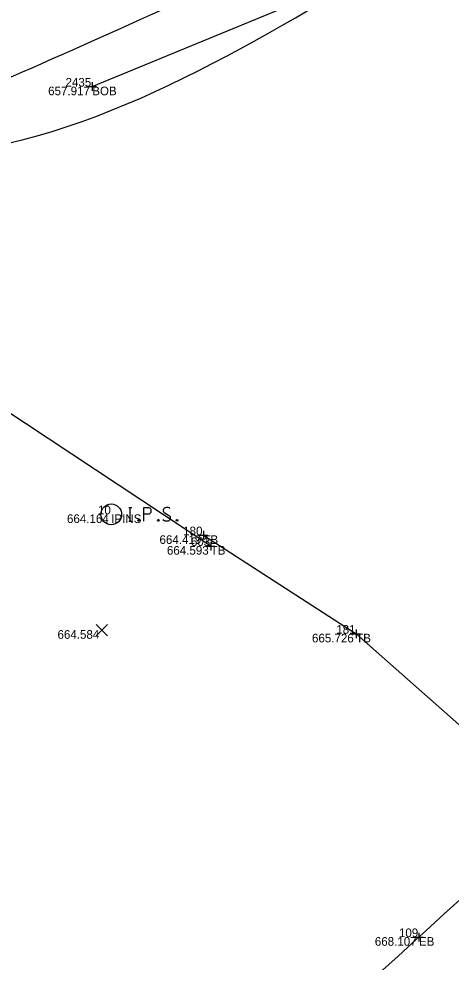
# Model space of a CAD drawing. Extents: x 2197382 to 2204062, y 634117 to 636522.
# Drawn here: x 2202463 to 2202513, y 635122.7 to 635231.8 of the extents above; entities that cross this region are included whole.
import ezdxf

# ---------------------------------------------------------------- set-up
doc = ezdxf.new("R2010")
doc.units = 0
for name, color, linetype in [('_CIVIL_CONSTRUCTION', 7, 'Continuous'), ('BR_X_SV_Bottom_of_Beam', 7, 'Continuous'), ('BR_X_SV_Bottom_of_Beam_Text', 7, 'Continuous'), ('BR_X_SV_Deck_Top', 7, 'Continuous'), ('GE_P_Alignment_100_Distances', 7, 'Continuous'), ('GE_X_Alignment', 7, 'Continuous'), ('PF_P_Grade_Line', 7, 'Continuous'), ('RW_X_CL_100_Curve_Data', 7, 'Continuous'), ('SC_Scratch1', 7, 'Continuous'), ('SH_Border', 7, 'Continuous'), ('SH_Cut_Line', 7, 'Continuous'), ('SH_Data', 7, 'Continuous')]:
    doc.layers.add(name, color=color, linetype=linetype)

msp = doc.modelspace()

# ---------------------------------------------------------------- linework, layer by layer
at = {"layer": '_CIVIL_CONSTRUCTION'}
for p, q in [((2202471.48, 635224.49), (2202471.48, 635223.49)), ((2202470.98, 635223.99), (2202471.98, 635223.99)), ((2202471.48, 635223.99), (2202471.48, 635223.99)), ((2202483.84, 635172.09), (2202484.84, 635172.09)), ((2202484.34, 635172.59), (2202484.34, 635171.59)), ((2202484.34, 635172.09), (2202484.34, 635172.09)), ((2202485.18, 635171.35), (2202485.18, 635170.35)), ((2202484.68, 635170.85), (2202485.68, 635170.85)), ((2202485.18, 635170.85), (2202485.18, 635170.85)), ((2202502.01, 635161.2), (2202502.01, 635160.2)), ((2202501.51, 635160.7), (2202502.51, 635160.7)), ((2202502.01, 635160.7), (2202502.01, 635160.7)), ((2202508.77, 635125.61), (2202509.77, 635125.61)), ((2202509.27, 635126.11), (2202509.27, 635125.11)), ((2202509.27, 635125.61), (2202509.27, 635125.61))]:
    msp.add_line(p, q, dxfattribs=at)
at = {"layer": 'BR_X_SV_Bottom_of_Beam'}
msp.add_line((2202471.48, 635223.99), (2202495.2, 635233.74), dxfattribs=at)
at = {"layer": 'BR_X_SV_Deck_Top'}
msp.add_open_spline([(2202458.05, 635216.68), (2202477.12, 635219.98), (2202511.72, 635243.78), (2202554.96, 635262.3), (2202588.01, 635280.67), (2202608.34, 635292.39), (2202640.83, 635312.14), (2202668.15, 635329.95), (2202698.57, 635351.31), (2202722.13, 635368.65), (2202754.6, 635393.43), (2202777.49, 635412.29), (2202789.61, 635422.64)], degree=3, dxfattribs=at)
at = {"layer": 'GE_P_Alignment_100_Distances'}
msp.add_open_spline([(2202457.67, 635223.28), (2202466.48, 635226.87), (2202500.46, 635242.35), (2202539.48, 635261.18), (2202573.06, 635279.52), (2202585.61, 635286.63), (2202599.84, 635294.84), (2202617.62, 635305.23), (2202642.29, 635320.4), (2202667.37, 635336.77), (2202691.72, 635353.63), (2202713.41, 635369.4), (2202739.64, 635388.97), (2202758.66, 635404.28), (2202770.06, 635413.81)], degree=3, dxfattribs=at)
at = {"layer": 'GE_X_Alignment'}
for points in [[(2202540.06, 635152.93), (2202529.43, 635144.25), (2202507.23, 635123.46), (2202471.72, 635092.05), (2202435.62, 635056.76), (2202402.1, 635018.87), (2202368.73, 634981.48), (2202336.15, 634943.25), (2202304.62, 634904.21), (2202274.11, 634864.33), (2202244.37, 634823.83), (2202215.65, 634782.83), (2202187.65, 634741.05), (2202161.54, 634698.56), (2202134.84, 634656), (2202111.41, 634611.66), (2202087.71, 634567.52), (2202064.97, 634523.35), (2202044.2, 634477.97), (2202023.42, 634432.25), (2202003.66, 634386.18), (2201990.91, 634355.55), (2201984.79, 634340.33)], [(2202570.92, 635145.14), (2202556.1, 635132.41), (2202530.6, 635107.02), (2202492.19, 635071.28), (2202457.98, 635035.82), (2202424.73, 634999.38), (2202391.64, 634962.22), (2202359.56, 634924.46), (2202328.32, 634885.6), (2202298.37, 634846.53), (2202268.85, 634806.21), (2202240.94, 634765.59), (2202212.91, 634724.71), (2202187.2, 634682.69), (2202161.14, 634640.35), (2202137.99, 634596.95), (2202114.64, 634553.56), (2202092.28, 634509.95), (2202071.73, 634464.7), (2202050.81, 634420.11), (2202031.84, 634374.34), (2202014.23, 634328.21), (2201997.98, 634281.03), (2201983.22, 634233.69), (2201972.74, 634202.38), (2201968.03, 634186.79)]]:
    msp.add_open_spline(points, degree=3, dxfattribs=at)
at = {"layer": 'PF_P_Grade_Line'}
for points in [[(2202485.18, 635170.85), (2202458.37, 635188.56), (2202433.67, 635197.97), (2202429.22, 635201.88)], [(2202484.34, 635172.09), (2202502.01, 635160.7), (2202520.5, 635144.4), (2202527.86, 635144.47)]]:
    msp.add_lwpolyline(points, dxfattribs=at)
at = {"layer": 'RW_X_CL_100_Curve_Data'}
for p, q in [((2202471.92, 635160.45), (2202473.25, 635161.79)), ((2202471.92, 635161.79), (2202473.25, 635160.45))]:
    msp.add_line(p, q, dxfattribs=at)
at = {"layer": 'SC_Scratch1'}
for points in [[(2202475.7, 635175.31), (2202476.05, 635175.31)], [(2202475.7, 635175.31), (2202476.05, 635175.31)], [(2202475.88, 635173.71), (2202475.88, 635175.31)], [(2202475.88, 635173.71), (2202475.88, 635175.31)], [(2202477.44, 635173.71), (2202477.44, 635175.31), (2202477.97, 635175.31), (2202478.03, 635175.3), (2202478.1, 635175.27), (2202478.14, 635175.25), (2202478.17, 635175.22), (2202478.21, 635175.16), (2202478.25, 635175.1), (2202478.27, 635175), (2202478.27, 635174.84), (2202478.26, 635174.79), (2202478.24, 635174.72), (2202478.19, 635174.63), (2202478.15, 635174.59), (2202478.11, 635174.57), (2202478.06, 635174.54), (2202477.97, 635174.53), (2202477.44, 635174.53)], [(2202477.44, 635173.71), (2202477.44, 635175.31), (2202477.97, 635175.31), (2202478.03, 635175.3), (2202478.1, 635175.27), (2202478.14, 635175.25), (2202478.17, 635175.22), (2202478.21, 635175.16), (2202478.25, 635175.1), (2202478.27, 635175), (2202478.27, 635174.84), (2202478.26, 635174.79), (2202478.24, 635174.72), (2202478.19, 635174.63), (2202478.15, 635174.59), (2202478.11, 635174.57), (2202478.06, 635174.54), (2202477.97, 635174.53), (2202477.44, 635174.53)], [(2202480.45, 635175.2), (2202480.43, 635175.22), (2202480.4, 635175.25), (2202480.3, 635175.29), (2202480.18, 635175.31), (2202480.09, 635175.31), (2202480.05, 635175.31), (2202479.91, 635175.27), (2202479.79, 635175.2), (2202479.71, 635175.1), (2202479.69, 635175), (2202479.69, 635174.92), (2202479.71, 635174.82), (2202479.8, 635174.73), (2202480.41, 635174.35), (2202480.46, 635174.3), (2202480.48, 635174.25), (2202480.51, 635174.18), (2202480.51, 635174.1), (2202480.5, 635174.03), (2202480.48, 635173.98), (2202480.46, 635173.91), (2202480.44, 635173.86), (2202480.42, 635173.82), (2202480.38, 635173.79), (2202480.35, 635173.76), (2202480.31, 635173.74), (2202480.27, 635173.72), (2202480.18, 635173.71), (2202480.02, 635173.71), (2202479.92, 635173.74), (2202479.78, 635173.82), (2202479.69, 635173.9)], [(2202480.45, 635175.2), (2202480.43, 635175.22), (2202480.4, 635175.25), (2202480.3, 635175.29), (2202480.18, 635175.31), (2202480.09, 635175.31), (2202480.05, 635175.31), (2202479.91, 635175.27), (2202479.79, 635175.2), (2202479.71, 635175.1), (2202479.69, 635175), (2202479.69, 635174.92), (2202479.71, 635174.82), (2202479.8, 635174.73), (2202480.41, 635174.35), (2202480.46, 635174.3), (2202480.48, 635174.25), (2202480.51, 635174.18), (2202480.51, 635174.1), (2202480.5, 635174.03), (2202480.48, 635173.98), (2202480.46, 635173.91), (2202480.44, 635173.86), (2202480.42, 635173.82), (2202480.38, 635173.79), (2202480.35, 635173.76), (2202480.31, 635173.74), (2202480.27, 635173.72), (2202480.18, 635173.71), (2202480.02, 635173.71), (2202479.92, 635173.74), (2202479.78, 635173.82), (2202479.69, 635173.9)], [(2202475.7, 635173.71), (2202476.05, 635173.71)], [(2202475.7, 635173.71), (2202476.05, 635173.71)], [(2202476.84, 635173.92), (2202476.89, 635173.92), (2202476.92, 635173.9), (2202476.96, 635173.85), (2202476.96, 635173.79), (2202476.92, 635173.74), (2202476.89, 635173.71), (2202476.84, 635173.71), (2202476.8, 635173.74), (2202476.77, 635173.79), (2202476.77, 635173.85), (2202476.8, 635173.9), (2202476.84, 635173.92)], [(2202476.84, 635173.92), (2202476.89, 635173.92), (2202476.92, 635173.9), (2202476.96, 635173.85), (2202476.96, 635173.79), (2202476.92, 635173.74), (2202476.89, 635173.71), (2202476.84, 635173.71), (2202476.8, 635173.74), (2202476.77, 635173.79), (2202476.77, 635173.85), (2202476.8, 635173.9), (2202476.84, 635173.92)], [(2202479.08, 635173.92), (2202479.14, 635173.92), (2202479.17, 635173.9), (2202479.21, 635173.85), (2202479.21, 635173.79), (2202479.17, 635173.74), (2202479.14, 635173.71), (2202479.08, 635173.71), (2202479.05, 635173.74), (2202479.02, 635173.79), (2202479.02, 635173.85), (2202479.05, 635173.9), (2202479.08, 635173.92)], [(2202479.08, 635173.92), (2202479.14, 635173.92), (2202479.17, 635173.9), (2202479.21, 635173.85), (2202479.21, 635173.79), (2202479.17, 635173.74), (2202479.14, 635173.71), (2202479.08, 635173.71), (2202479.05, 635173.74), (2202479.02, 635173.79), (2202479.02, 635173.85), (2202479.05, 635173.9), (2202479.08, 635173.92)], [(2202481.27, 635173.92), (2202481.32, 635173.92), (2202481.35, 635173.9), (2202481.39, 635173.85), (2202481.39, 635173.79), (2202481.35, 635173.74), (2202481.32, 635173.71), (2202481.27, 635173.71), (2202481.23, 635173.74), (2202481.2, 635173.79), (2202481.2, 635173.85), (2202481.23, 635173.9), (2202481.27, 635173.92)], [(2202481.27, 635173.92), (2202481.32, 635173.92), (2202481.35, 635173.9), (2202481.39, 635173.85), (2202481.39, 635173.79), (2202481.35, 635173.74), (2202481.32, 635173.71), (2202481.27, 635173.71), (2202481.23, 635173.74), (2202481.2, 635173.79), (2202481.2, 635173.85), (2202481.23, 635173.9), (2202481.27, 635173.92)]]:
    msp.add_lwpolyline(points, dxfattribs=at)
msp.add_circle((2202473.68, 635174.51), 1.2, dxfattribs=at)
msp.add_circle((2202473.68, 635174.51), 1.2, dxfattribs=at)

# ---------------------------------------------------------------- texts
at = {"layer": 'BR_X_SV_Bottom_of_Beam_Text'}
for s, p in [('2435', (2202468.39, 635223.99)), ('657.917', (2202466.38, 635222.99)), ('BOB', (2202471.48, 635222.99))]:
    msp.add_text(s, height=1, dxfattribs=at).set_placement(p)
at = {"layer": 'SH_Border'}
for s, p in [('IPINS', (2202473.68, 635173.51)), ('IPINS', (2202473.68, 635173.51)), ('TB', (2202484.34, 635171.09)), ('TB', (2202485.18, 635169.85)), ('TB', (2202502.01, 635159.7)), ('EB', (2202509.27, 635124.61))]:
    msp.add_text(s, height=1, dxfattribs=at).set_placement(p)
at = {"layer": 'SH_Cut_Line'}
for s, p in [('10', (2202472.14, 635174.51)), ('10', (2202472.14, 635174.51)), ('180', (2202482, 635172.09)), ('603', (2202482.89, 635170.85)), ('181', (2202499.71, 635160.7)), ('109', (2202506.96, 635125.61))]:
    msp.add_text(s, height=1, dxfattribs=at).set_placement(p)
at = {"layer": 'SH_Data'}
for s, p in [('664.164', (2202468.56, 635173.51)), ('664.164', (2202468.56, 635173.51)), ('664.419', (2202479.26, 635171.09)), ('664.593', (2202480.12, 635169.85)), ('664.584', (2202467.46, 635160.12)), ('665.726', (2202496.9, 635159.7)), ('668.107', (2202504.17, 635124.61))]:
    msp.add_text(s, height=1, dxfattribs=at).set_placement(p)

doc.saveas('drawing.dxf')
